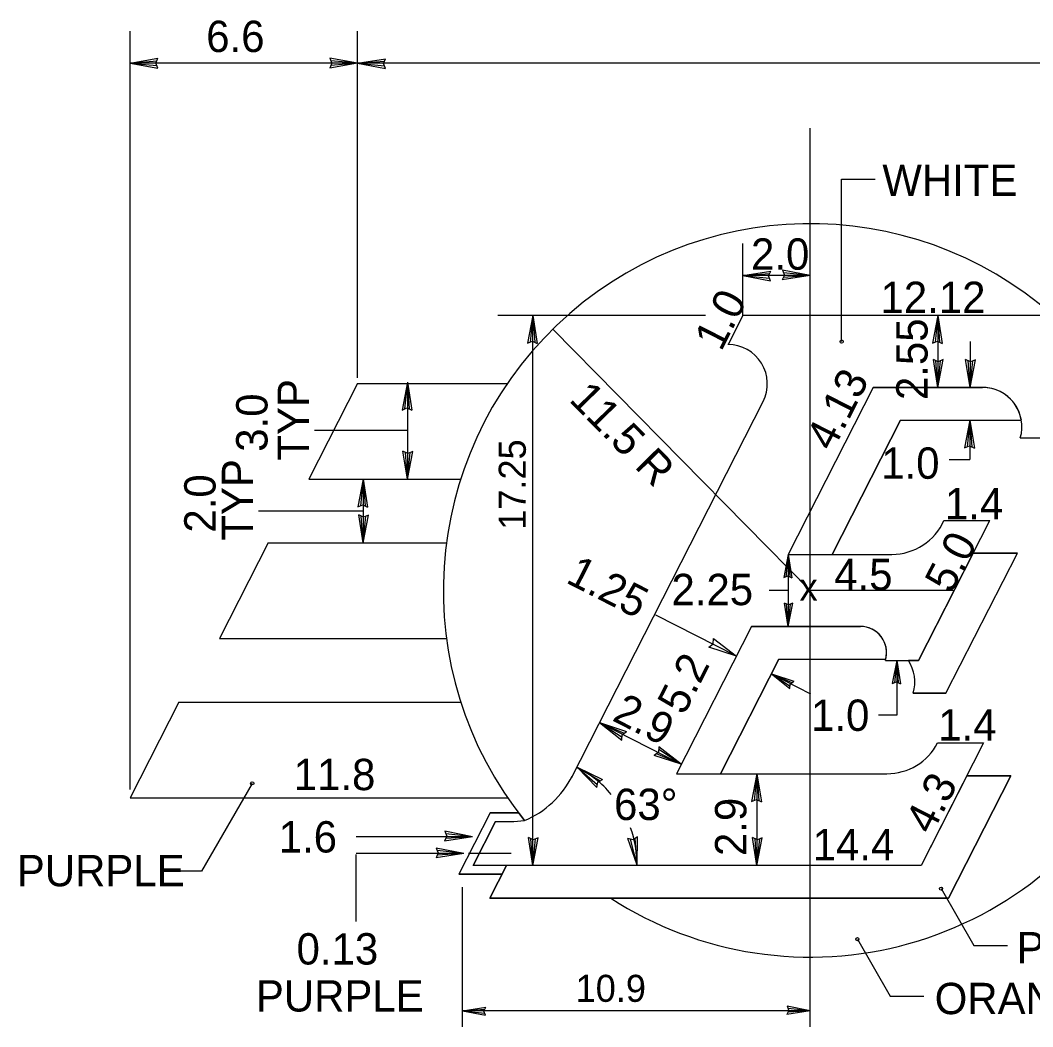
# Model space of a CAD drawing. Extents: x 10268197 to 10269179, y 2141503 to 2142677.
# Drawn here: x 10268462.18 to 10268484.78, y 2142084.09 to 2142106.56 of the extents above; entities that cross this region are included whole.
import ezdxf

# ---------------------------------------------------------------- set-up
doc = ezdxf.new("R2010")
doc.units = 0
for name, color, linetype in [('1', 7, 'Continuous'), ('2', 7, 'Continuous'), ('20', 7, 'Continuous'), ('21', 7, 'Continuous'), ('3', 7, 'Continuous'), ('52', 7, 'Continuous')]:
    doc.layers.add(name, color=color, linetype=linetype)

msp = doc.modelspace()

# ---------------------------------------------------------------- linework, layer by layer
at = {"layer": '1'}
for p, q in [((10268479.81, 2142093.833), (10268479.81, 2142104.155)), ((10268478.307, 2142099.972), (10268477.976, 2142099.322)), ((10268486.932, 2142099.972), (10268478.307, 2142099.972)), ((10268479.81, 2142093.833), (10268474.065, 2142099.665)), ((10268469.71, 2142098.453), (10268468.622, 2142096.317)), ((10268469.71, 2142098.453), (10268473.052, 2142098.453)), ((10268481.218, 2142098.365), (10268479.319, 2142094.636)), ((10268481.218, 2142098.365), (10268479.319, 2142094.636)), ((10268481.218, 2142098.365), (10268483.658, 2142098.365)), ((10268483.658, 2142098.365), (10268481.218, 2142098.365)), ((10268474.48, 2142089.649), (10268478.759, 2142098.047)), ((10268481.829, 2142097.634), (10268480.302, 2142094.636)), ((10268480.302, 2142094.636), (10268481.829, 2142097.634)), ((10268481.829, 2142097.634), (10268484.523, 2142097.634)), ((10268481.829, 2142097.634), (10268484.523, 2142097.634)), ((10268470.821, 2142097.399), (10268468.75, 2142097.399)), ((10268484.499, 2142097.237), (10268485.539, 2142097.238)), ((10268468.622, 2142096.317), (10268472.009, 2142096.317)), ((10268469.832, 2142095.605), (10268467.495, 2142095.605)), ((10268482.229, 2142092.269), (10268483.821, 2142095.396)), ((10268482.796, 2142095.396), (10268483.821, 2142095.396)), ((10268467.715, 2142094.893), (10268466.625, 2142092.758)), ((10268467.715, 2142094.893), (10268471.692, 2142094.893)), ((10268479.319, 2142094.636), (10268481.631, 2142094.636)), ((10268479.319, 2142094.636), (10268480.302, 2142094.636)), ((10268483.449, 2142094.664), (10268482.229, 2142092.269)), ((10268482.84, 2142091.538), (10268484.434, 2142094.665)), ((10268482.84, 2142091.538), (10268484.434, 2142094.665)), ((10268483.449, 2142094.664), (10268484.434, 2142094.665)), ((10268484.434, 2142094.665), (10268483.449, 2142094.664)), ((10268479.319, 2142093.832), (10268478.894, 2142093.832)), ((10268479.81, 2142084.091), (10268479.81, 2142093.833)), ((10268483.025, 2142093.833), (10268479.81, 2142093.833)), ((10268478.5, 2142093.028), (10268476.824, 2142089.739)), ((10268478.5, 2142093.028), (10268476.824, 2142089.739)), ((10268478.5, 2142093.028), (10268480.93, 2142093.028)), ((10268480.93, 2142093.028), (10268478.5, 2142093.028)), ((10268466.625, 2142092.758), (10268471.694, 2142092.758)), ((10268479.111, 2142092.298), (10268477.808, 2142089.739)), ((10268477.808, 2142089.739), (10268479.111, 2142092.298)), ((10268479.111, 2142092.298), (10268481.497, 2142092.298)), ((10268479.111, 2142092.298), (10268481.497, 2142092.298)), ((10268481.488, 2142092.269), (10268482.229, 2142092.269)), ((10268482.229, 2142092.269), (10268482.002, 2142092.27)), ((10268482.84, 2142091.538), (10268482.109, 2142091.538)), ((10268482.109, 2142091.538), (10268482.84, 2142091.538)), ((10268465.719, 2142091.334), (10268464.63, 2142089.198)), ((10268465.719, 2142091.334), (10268472.014, 2142091.334)), ((10268483.678, 2142090.428), (10268482.284, 2142087.692)), ((10268482.654, 2142090.428), (10268483.678, 2142090.428)), ((10268476.824, 2142089.739), (10268481.52, 2142089.739)), ((10268476.824, 2142089.739), (10268477.808, 2142089.739)), ((10268483.306, 2142089.696), (10268482.284, 2142087.692)), ((10268484.29, 2142089.696), (10268482.896, 2142086.961)), ((10268482.896, 2142086.961), (10268484.29, 2142089.696)), ((10268483.306, 2142089.696), (10268484.29, 2142089.696)), ((10268484.29, 2142089.696), (10268483.306, 2142089.696)), ((10268464.63, 2142089.198), (10268473.061, 2142089.198)), ((10268482.284, 2142087.692), (10268472.288, 2142087.692)), ((10268472.662, 2142086.961), (10268473.034, 2142087.692)), ((10268473.034, 2142087.692), (10268472.662, 2142086.961)), ((10268482.284, 2142087.692), (10268473.034, 2142087.692)), ((10268472.935, 2142087.497), (10268471.97, 2142087.497)), ((10268472.05, 2142084.091), (10268472.05, 2142087.21)), ((10268482.896, 2142086.961), (10268472.662, 2142086.961)), ((10268472.662, 2142086.961), (10268482.896, 2142086.961))]:
    msp.add_line(p, q, dxfattribs=at)
for centre, radius, start, end in [((10268479.81, 2142093.833), 8.187, 48.5904, 218.8792), ((10268477.977, 2142098.445), 0.877, 333.0033, 90.1042), ((10268483.659, 2142097.487), 0.877, 343.4611, 90), ((10268483.659, 2142097.487), 0.877, 9.5941, 90), ((10268481.632, 2142095.909), 1.272, 270, 336.2493), ((10268480.93, 2142092.444), 0.585, 342.6625, 90), ((10268480.93, 2142092.444), 0.585, 345.5225, 90), ((10268481.269, 2142091.788), 0.877, 343.4611, 33.2756), ((10268481.269, 2142091.788), 0.877, 343.4611, 33.2756), ((10268479.81, 2142093.833), 8.187, 237.0648, 334.1734), ((10268481.519, 2142091.018), 1.279, 270, 332.5096), ((10268472.597, 2142090.658), 2.136, 293.1567, 333.0112)]:
    msp.add_arc(centre, radius, start, end, dxfattribs=at)
at = {"layer": '2'}
for p, q in [((10268472.668, 2142088.87), (10268471.97, 2142087.497)), ((10268472.668, 2142088.87), (10268473.305, 2142088.87)), ((10268472.788, 2142088.675), (10268472.288, 2142087.692))]:
    msp.add_line(p, q, dxfattribs=at)
at = {"layer": '20'}
for p, q in [((10268464.63, 2142089.388), (10268464.63, 2142106.316)), ((10268469.71, 2142099.615), (10268469.71, 2142106.316)), ((10268469.71, 2142105.604), (10268464.63, 2142105.604)), ((10268516.747, 2142105.604), (10268469.71, 2142105.604)), ((10268480.512, 2142099.388), (10268480.512, 2142103.011)), ((10268480.512, 2142103.011), (10268481.262, 2142103.011)), ((10268478.307, 2142099.972), (10268478.307, 2142101.575)), ((10268479.81, 2142100.863), (10268478.307, 2142100.863)), ((10268477.47, 2142099.972), (10268472.839, 2142099.973)), ((10268473.62, 2142087.692), (10268473.619, 2142099.972)), ((10268482.658, 2142099.972), (10268482.658, 2142098.365)), ((10268469.71, 2142098.577), (10268469.71, 2142099.615)), ((10268483.378, 2142099.391), (10268483.378, 2142098.364)), ((10268470.82, 2142098.48), (10268470.821, 2142096.317)), ((10268483.377, 2142097.634), (10268483.377, 2142096.757)), ((10268482.914, 2142096.757), (10268483.377, 2142096.757)), ((10268469.832, 2142096.317), (10268469.832, 2142094.893)), ((10268479.319, 2142094.636), (10268479.319, 2142093.028)), ((10268478.162, 2142092.366), (10268476.362, 2142093.283)), ((10268481.743, 2142092.269), (10268481.743, 2142091.046)), ((10268478.943, 2142091.968), (10268479.818, 2142091.522)), ((10268481.743, 2142091.046), (10268481.335, 2142091.046)), ((10268475.107, 2142090.88), (10268476.932, 2142089.951)), ((10268478.621, 2142089.739), (10268478.621, 2142087.692)), ((10268467.357, 2142089.524), (10268466.224, 2142087.563)), ((10268472.273, 2142088.333), (10268469.676, 2142088.333)), ((10268472.083, 2142087.961), (10268469.676, 2142087.961)), ((10268469.676, 2142086.441), (10268469.676, 2142087.938)), ((10268473.135, 2142087.961), (10268472.187, 2142087.961)), ((10268466.224, 2142087.563), (10268465.475, 2142087.562)), ((10268482.731, 2142087.174), (10268483.465, 2142085.903)), ((10268480.864, 2142086.046), (10268481.598, 2142084.774)), ((10268483.465, 2142085.903), (10268484.215, 2142085.903)), ((10268481.598, 2142084.774), (10268482.348, 2142084.774)), ((10268479.81, 2142084.448), (10268472.05, 2142084.448))]:
    msp.add_line(p, q, dxfattribs=at)
for centre in [(10268480.512, 2142099.388), (10268467.357, 2142089.524), (10268482.731, 2142087.174), (10268480.864, 2142086.046)]:
    msp.add_circle(centre, 0.0356, dxfattribs=at)
for start, end in [(40.0298, 62.999), (0, 19.9667)]:
    msp.add_arc((10268473.483, 2142087.692), 2.465, start, end, dxfattribs=at)
at = {"layer": '21'}
for p, q in [((10268464.63, 2142105.604), (10268465.252, 2142105.713)), ((10268464.63, 2142105.604), (10268465.226, 2142105.656)), ((10268465.204, 2142105.604), (10268465.252, 2142105.713)), ((10268469.71, 2142105.604), (10268469.088, 2142105.713)), ((10268469.088, 2142105.713), (10268469.136, 2142105.604)), ((10268469.71, 2142105.604), (10268469.113, 2142105.656)), ((10268469.71, 2142105.604), (10268470.334, 2142105.703)), ((10268469.71, 2142105.604), (10268470.307, 2142105.645)), ((10268470.284, 2142105.594), (10268470.334, 2142105.703)), ((10268464.63, 2142105.604), (10268465.251, 2142105.494)), ((10268464.63, 2142105.604), (10268465.227, 2142105.552)), ((10268465.251, 2142105.494), (10268465.204, 2142105.604)), ((10268469.71, 2142105.604), (10268469.088, 2142105.494)), ((10268469.136, 2142105.604), (10268469.088, 2142105.494)), ((10268469.71, 2142105.604), (10268469.113, 2142105.552)), ((10268469.71, 2142105.604), (10268470.33, 2142105.483)), ((10268469.71, 2142105.604), (10268470.306, 2142105.541)), ((10268470.33, 2142105.483), (10268470.284, 2142105.594)), ((10268478.307, 2142100.863), (10268478.931, 2142100.962)), ((10268478.307, 2142100.863), (10268478.905, 2142100.905)), ((10268478.881, 2142100.853), (10268478.931, 2142100.962)), ((10268479.81, 2142100.863), (10268479.19, 2142100.983)), ((10268479.19, 2142100.983), (10268479.236, 2142100.873)), ((10268479.81, 2142100.863), (10268479.214, 2142100.925)), ((10268478.307, 2142100.863), (10268478.927, 2142100.743)), ((10268478.307, 2142100.863), (10268478.903, 2142100.801)), ((10268478.927, 2142100.743), (10268478.881, 2142100.853)), ((10268479.236, 2142100.873), (10268479.186, 2142100.764)), ((10268479.81, 2142100.863), (10268479.186, 2142100.764)), ((10268479.81, 2142100.863), (10268479.213, 2142100.821)), ((10268473.619, 2142099.972), (10268473.499, 2142099.352)), ((10268473.619, 2142099.972), (10268473.557, 2142099.376)), ((10268473.619, 2142099.972), (10268473.719, 2142099.348)), ((10268473.619, 2142099.972), (10268473.661, 2142099.375)), ((10268482.658, 2142099.972), (10268482.538, 2142099.352)), ((10268482.658, 2142099.972), (10268482.596, 2142099.376)), ((10268482.658, 2142099.972), (10268482.757, 2142099.348)), ((10268482.658, 2142099.972), (10268482.7, 2142099.375)), ((10268473.499, 2142099.352), (10268473.61, 2142099.398)), ((10268473.61, 2142099.398), (10268473.719, 2142099.348)), ((10268482.538, 2142099.352), (10268482.649, 2142099.398)), ((10268482.649, 2142099.398), (10268482.757, 2142099.348)), ((10268482.658, 2142098.365), (10268482.559, 2142098.988)), ((10268482.668, 2142098.939), (10268482.559, 2142098.988)), ((10268482.658, 2142098.365), (10268482.617, 2142098.962)), ((10268482.658, 2142098.365), (10268482.779, 2142098.985)), ((10268482.658, 2142098.365), (10268482.721, 2142098.961)), ((10268482.779, 2142098.985), (10268482.668, 2142098.939)), ((10268483.378, 2142098.364), (10268483.279, 2142098.988)), ((10268483.387, 2142098.939), (10268483.279, 2142098.988)), ((10268483.378, 2142098.364), (10268483.336, 2142098.962)), ((10268483.378, 2142098.364), (10268483.498, 2142098.984)), ((10268483.378, 2142098.364), (10268483.44, 2142098.961)), ((10268483.498, 2142098.984), (10268483.387, 2142098.939)), ((10268470.82, 2142098.48), (10268470.7, 2142097.86)), ((10268470.82, 2142098.48), (10268470.758, 2142097.884)), ((10268470.82, 2142098.48), (10268470.919, 2142097.856)), ((10268470.82, 2142098.48), (10268470.862, 2142097.883)), ((10268470.7, 2142097.86), (10268470.811, 2142097.906)), ((10268470.811, 2142097.906), (10268470.919, 2142097.856)), ((10268483.377, 2142097.634), (10268483.257, 2142097.014)), ((10268483.377, 2142097.634), (10268483.315, 2142097.038)), ((10268483.377, 2142097.634), (10268483.477, 2142097.01)), ((10268483.377, 2142097.634), (10268483.419, 2142097.036)), ((10268483.257, 2142097.014), (10268483.368, 2142097.059)), ((10268483.368, 2142097.059), (10268483.477, 2142097.01)), ((10268470.821, 2142096.317), (10268470.722, 2142096.941)), ((10268470.831, 2142096.891), (10268470.722, 2142096.941)), ((10268470.821, 2142096.317), (10268470.779, 2142096.915)), ((10268470.821, 2142096.317), (10268470.941, 2142096.937)), ((10268470.821, 2142096.317), (10268470.883, 2142096.913)), ((10268470.941, 2142096.937), (10268470.831, 2142096.891)), ((10268469.832, 2142096.317), (10268469.712, 2142095.697)), ((10268469.832, 2142096.317), (10268469.77, 2142095.721)), ((10268469.832, 2142096.317), (10268469.931, 2142095.694)), ((10268469.832, 2142096.317), (10268469.874, 2142095.72)), ((10268469.712, 2142095.697), (10268469.822, 2142095.743)), ((10268469.822, 2142095.743), (10268469.931, 2142095.694)), ((10268469.832, 2142094.893), (10268469.733, 2142095.517)), ((10268469.842, 2142095.467), (10268469.733, 2142095.517)), ((10268469.832, 2142094.893), (10268469.79, 2142095.49)), ((10268469.832, 2142094.893), (10268469.953, 2142095.513)), ((10268469.832, 2142094.893), (10268469.894, 2142095.489)), ((10268469.953, 2142095.513), (10268469.842, 2142095.467)), ((10268479.319, 2142094.636), (10268479.219, 2142094.119)), ((10268479.319, 2142094.636), (10268479.267, 2142094.139)), ((10268479.319, 2142094.636), (10268479.402, 2142094.116)), ((10268479.319, 2142094.636), (10268479.354, 2142094.138)), ((10268479.219, 2142094.119), (10268479.311, 2142094.157)), ((10268479.311, 2142094.157), (10268479.402, 2142094.116)), ((10268479.319, 2142093.028), (10268479.237, 2142093.549)), ((10268479.327, 2142093.508), (10268479.237, 2142093.549)), ((10268479.319, 2142093.028), (10268479.284, 2142093.527)), ((10268479.319, 2142093.028), (10268479.42, 2142093.545)), ((10268479.319, 2142093.028), (10268479.371, 2142093.525)), ((10268479.42, 2142093.545), (10268479.327, 2142093.508)), ((10268481.743, 2142092.269), (10268481.643, 2142091.752)), ((10268481.743, 2142092.269), (10268481.691, 2142091.772)), ((10268481.743, 2142092.269), (10268481.825, 2142091.749)), ((10268481.743, 2142092.269), (10268481.777, 2142091.771)), ((10268478.943, 2142091.968), (10268479.445, 2142091.806)), ((10268478.943, 2142091.968), (10268479.359, 2142091.644)), ((10268478.943, 2142091.968), (10268479.362, 2142091.697)), ((10268478.943, 2142091.968), (10268479.403, 2142091.773)), ((10268479.359, 2142091.644), (10268479.367, 2142091.743)), ((10268479.367, 2142091.743), (10268479.445, 2142091.806)), ((10268481.643, 2142091.752), (10268481.735, 2142091.79)), ((10268481.735, 2142091.79), (10268481.825, 2142091.749)), ((10268475.107, 2142090.88), (10268475.708, 2142090.685)), ((10268475.107, 2142090.88), (10268475.605, 2142090.492)), ((10268475.107, 2142090.88), (10268475.61, 2142090.554)), ((10268475.107, 2142090.88), (10268475.658, 2142090.646)), ((10268475.605, 2142090.492), (10268475.614, 2142090.611)), ((10268475.614, 2142090.611), (10268475.708, 2142090.685)), ((10268476.434, 2142090.339), (10268476.425, 2142090.22)), ((10268476.932, 2142089.951), (10268476.429, 2142090.277)), ((10268476.932, 2142089.951), (10268476.434, 2142090.339)), ((10268476.425, 2142090.22), (10268476.331, 2142090.146)), ((10268476.932, 2142089.951), (10268476.331, 2142090.146)), ((10268476.932, 2142089.951), (10268476.38, 2142090.185)), ((10268474.606, 2142089.888), (10268475.174, 2142089.614)), ((10268474.606, 2142089.888), (10268475.046, 2142089.436)), ((10268474.606, 2142089.888), (10268475.059, 2142089.497)), ((10268474.606, 2142089.888), (10268475.12, 2142089.582)), ((10268475.072, 2142089.553), (10268475.174, 2142089.614)), ((10268478.621, 2142089.739), (10268478.501, 2142089.119)), ((10268478.621, 2142089.739), (10268478.559, 2142089.143)), ((10268478.621, 2142089.739), (10268478.72, 2142089.115)), ((10268478.621, 2142089.739), (10268478.663, 2142089.141)), ((10268475.046, 2142089.436), (10268475.072, 2142089.553)), ((10268478.501, 2142089.119), (10268478.612, 2142089.164)), ((10268478.612, 2142089.164), (10268478.72, 2142089.115)), ((10268472.273, 2142088.333), (10268471.653, 2142088.454)), ((10268471.653, 2142088.454), (10268471.699, 2142088.343)), ((10268471.699, 2142088.343), (10268471.649, 2142088.234)), ((10268472.273, 2142088.333), (10268471.649, 2142088.234)), ((10268472.273, 2142088.333), (10268471.676, 2142088.291)), ((10268472.273, 2142088.333), (10268471.677, 2142088.395)), ((10268473.62, 2142087.692), (10268473.521, 2142088.316)), ((10268473.629, 2142088.266), (10268473.521, 2142088.316)), ((10268473.62, 2142087.692), (10268473.578, 2142088.289)), ((10268473.62, 2142087.692), (10268473.74, 2142088.312)), ((10268473.62, 2142087.692), (10268473.682, 2142088.288)), ((10268473.74, 2142088.312), (10268473.629, 2142088.266)), ((10268475.948, 2142087.696), (10268475.742, 2142088.293)), ((10268475.858, 2142088.264), (10268475.742, 2142088.293)), ((10268475.948, 2142087.696), (10268475.803, 2142088.277)), ((10268475.959, 2142088.328), (10268475.858, 2142088.264)), ((10268475.948, 2142087.696), (10268475.905, 2142088.294)), ((10268475.948, 2142087.696), (10268475.959, 2142088.328)), ((10268478.621, 2142087.692), (10268478.523, 2142088.316)), ((10268478.631, 2142088.266), (10268478.523, 2142088.316)), ((10268478.621, 2142087.692), (10268478.58, 2142088.289)), ((10268478.621, 2142087.692), (10268478.742, 2142088.312)), ((10268478.621, 2142087.692), (10268478.684, 2142088.288)), ((10268478.742, 2142088.312), (10268478.631, 2142088.266)), ((10268472.083, 2142087.961), (10268471.463, 2142088.081)), ((10268471.463, 2142088.081), (10268471.509, 2142087.971)), ((10268472.083, 2142087.961), (10268471.487, 2142088.023)), ((10268471.509, 2142087.971), (10268471.46, 2142087.862)), ((10268472.083, 2142087.961), (10268471.46, 2142087.862)), ((10268472.083, 2142087.961), (10268471.486, 2142087.919)), ((10268472.05, 2142084.448), (10268472.57, 2142084.531)), ((10268472.05, 2142084.448), (10268472.548, 2142084.483)), ((10268472.05, 2142084.448), (10268472.567, 2142084.348)), ((10268472.05, 2142084.448), (10268472.548, 2142084.396)), ((10268472.529, 2142084.44), (10268472.57, 2142084.531)), ((10268472.567, 2142084.348), (10268472.529, 2142084.44)), ((10268479.331, 2142084.457), (10268479.29, 2142084.366)), ((10268479.81, 2142084.448), (10268479.29, 2142084.366)), ((10268479.81, 2142084.448), (10268479.293, 2142084.549)), ((10268479.293, 2142084.549), (10268479.331, 2142084.457)), ((10268479.81, 2142084.448), (10268479.312, 2142084.414)), ((10268479.81, 2142084.448), (10268479.313, 2142084.501))]:
    msp.add_line(p, q, dxfattribs=at)
at = {"layer": '3'}
for p, q in [((10268473.198, 2142088.675), (10268473.437, 2142088.694)), ((10268472.788, 2142088.675), (10268473.198, 2142088.675))]:
    msp.add_line(p, q, dxfattribs=at)
msp.add_lwpolyline([(10268473.305, 2142088.87), (10268472.668, 2142088.87), (10268471.97, 2142087.497), (10268472.935, 2142087.497), (10268473.034, 2142087.692), (10268472.288, 2142087.692), (10268472.788, 2142088.675), (10268473.198, 2142088.675), (10268473.437, 2142088.694)], close=True, dxfattribs=at)
at = {"layer": '52'}
msp.add_lwpolyline([(10268478.162, 2142092.366), (10268477.55, 2142092.565), (10268477.642, 2142092.641), (10268477.655, 2142092.761)], close=True, dxfattribs=at)

# ---------------------------------------------------------------- texts
at = {"layer": '1'}
msp.add_text('x', height=0.604, dxfattribs=at).set_placement((10268479.572, 2142093.605))
at = {"layer": '20'}
for s, height, p in [('6.6', 0.7, (10268466.33, 2142105.852)), ('WHITE', 0.7, (10268481.42, 2142102.64)), ('2.0', 0.7, (10268478.49, 2142100.992)), ('12.12', 0.7, (10268481.38, 2142100.026)), ('1.0', 0.7, (10268481.396, 2142096.325)), ('1.4', 0.7, (10268482.818, 2142095.42)), ('4.5', 0.7, (10268480.347, 2142093.838)), ('1.0', 0.7, (10268479.83, 2142090.696)), ('1.4', 0.7, (10268482.668, 2142090.481)), ('11.8', 0.7, (10268468.284, 2142089.373)), ('63°', 0.7, (10268475.433, 2142088.706)), ('1.6', 0.7, (10268467.948, 2142087.981)), ('14.4', 0.7, (10268479.866, 2142087.806)), ('PURPLE', 0.7, (10268462.103, 2142087.227)), ('PURPLE', 0.7, (10268484.419, 2142085.505)), ('0.13', 0.7, (10268468.347, 2142085.48)), ('PURPLE', 0.7, (10268467.438, 2142084.43)), ('10.9', 0.6037, (10268474.574, 2142084.647)), ('ORANGE', 0.7, (10268482.589, 2142084.372))]:
    msp.add_text(s, height=height, dxfattribs=at).set_placement(p)
for s, height, rotation, p in [('1.0', 0.7, 62.9854, (10268477.821, 2142099.148)), ('2.55', 0.7, 90, (10268482.43, 2142098.083)), ('4.13', 0.7, 63.012, (10268480.31, 2142096.914)), ('TYP', 0.7, 90, (10268468.624, 2142096.731)), ('11.5 R', 0.7, 314.5624, (10268474.407, 2142098.072)), ('3.0', 0.7, 90, (10268467.698, 2142096.928)), ('17.25', 0.6037, 90, (10268473.463, 2142095.185)), ('TYP', 0.7, 90, (10268467.377, 2142094.943)), ('2.0', 0.7, 90, (10268466.539, 2142095.123)), ('5.0', 0.7, 63.0087, (10268482.962, 2142093.739)), ('1.25', 0.7, 333.0041, (10268474.331, 2142094.019)), ('2.25', 0.7, 360, (10268476.714, 2142093.503)), ('5.2', 0.7, 63.0001, (10268476.994, 2142091.025)), ('2.9', 0.7, 333.0028, (10268475.366, 2142090.94)), ('4.3', 0.7, 62.9952, (10268482.523, 2142088.357)), ('2.9', 0.7, 90, (10268478.386, 2142087.902))]:
    msp.add_text(s, height=height, rotation=rotation, dxfattribs=at).set_placement(p)

doc.saveas('drawing.dxf')
